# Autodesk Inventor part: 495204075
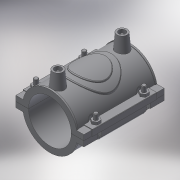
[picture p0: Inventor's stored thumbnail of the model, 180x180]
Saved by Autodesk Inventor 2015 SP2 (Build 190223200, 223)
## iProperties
Created: 2017-07
Part Number: 495204075
Material: Generic
Description: PLASSON REPAIR SADDLE 75
Document SubType Name: Modeling
Designer: KIM
Density: 1 g/cm^3
Appearance: Default
Author: KIM
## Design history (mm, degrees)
derived "495204.ipt"
feature "Solid1::495204.ipt"
tag "TaggingFeature1"
body "Solid1"
other parameters: "d0" = 75, "d1" = 97.5, "d2" = 117, "d3" = 18.75, "d4" = 118, "d5" = 0, "d6" = 0.1, "d8" = 0, "d19" = 6, "d20" = 6, "d21" = 70.8, "d23" = 0, "d24" = 35.4, "d26" = 0, "d27" = 3, "d28" = 3, "d29" = 3, "d30" = 25, "d31" = 6, "d32" = 0, "d33" = 0, "d34" = 0.6, "d40" = 50.7, "d41" = 64.9, "d43" = 0, "d45" = 0, "d47" = 52.65, "d48" = 47.2, "d50" = 0, "d70" = 15, "d72" = 0, "d73" = 6, "d75" = 5, "d76" = 0, "d77" = 3.75, "d78" = 66.5, "d79" = 15, "d80" = 47.2, "d82" = 5 deg, "d84" = 4, "d85" = 14, "d86" = 0, "d87" = 3, "d88" = 0, "d89" = 1, "d90" = 1, "d91" = 94.4, "d92" = 0, "d93" = 0.5, "d94" = 39.47368, "d96" = 99.45, "d97" = 2.36, "d98" = 0, "d99" = 47.2, "d100" = 0, "d102" = 2.36, "d_" = 75, "B_" = 117, "H_" = 29, "L_" = 118, "d_t" = 6
